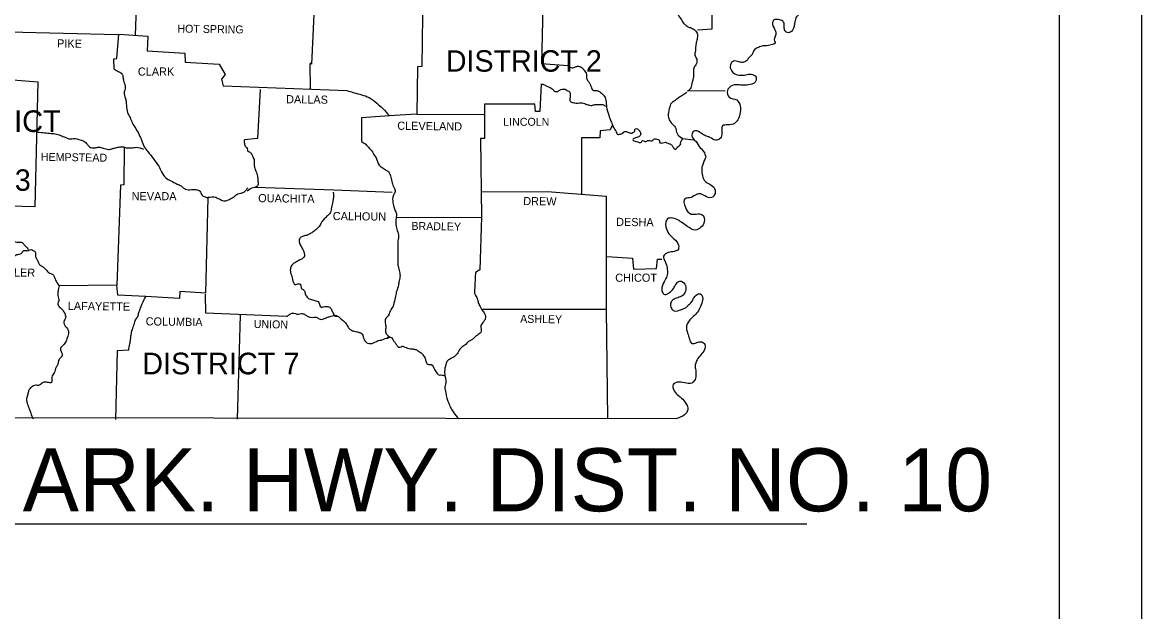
# Model space of a CAD drawing. Extents: x 1369885 to 1370219, y 379980 to 380218.
# Drawn here: x 1370154 to 1370218.7, y 380128.7 to 380162.7 of the extents above; entities that cross this region are included whole.
import ezdxf

# ---------------------------------------------------------------- set-up
doc = ezdxf.new("R2010")
doc.units = 0
for name, color, linetype in [('Default', 7, 'Continuous'), ('Level 2', 7, 'Continuous'), ('R_No Plot', 7, 'Continuous'), ('STAMP_PE_FOSTER-SIGNATURE', 7, 'Continuous')]:
    doc.layers.add(name, color=color, linetype=linetype)

msp = doc.modelspace()

# ---------------------------------------------------------------- linework, layer by layer
at = {"layer": 'Default'}
for p, q in [((1370170.674, 380160.32), (1370170.76, 380160.406)), ((1370170.621, 380158.853), (1370170.665, 380158.897)), ((1370192.473, 380158.751), (1370194.665, 380158.781)), ((1370192.174, 380156.012), (1370192.862, 380155.922)), ((1370161.151, 380146.826), (1370161.171, 380146.866)), ((1370149.848, 380133.736), (1370199.392, 380133.736))]:
    msp.add_line(p, q, dxfattribs=at)
for points in [[(1370193.061, 380162.288), (1370193.918, 380162.348), (1370193.908, 380164.569), (1370193.111, 380164.629), (1370193.151, 380168.973), (1370192.463, 380169.072), (1370192.433, 380172.001), (1370201.788, 380172.071)], [(1370160.812, 380168.853), (1370160.551, 380161.977)], [(1370177.191, 380164.589), (1370177.131, 380160.166), (1370176.872, 380160.156), (1370176.842, 380157.406)], [(1370184.144, 380164.47), (1370184.055, 380160.345), (1370185.579, 380160.216)], [(1370170.884, 380163.165), (1370170.755, 380160.296), (1370170.655, 380160.325), (1370170.665, 380158.851)], [(1370153.261, 380162.258), (1370153.261, 380160.804), (1370153.5, 380160.754), (1370153.48, 380159.399), (1370154.925, 380159.289), (1370154.755, 380152.047), (1370151.767, 380152.126)], [(1370153.281, 380162.178), (1370159.547, 380162.019)], [(1370159.338, 380160.017), (1370159.318, 380160.614), (1370159.497, 380160.624), (1370159.607, 380162.039), (1370161.291, 380161.929), (1370161.251, 380161.063), (1370163.433, 380160.943), (1370163.443, 380160.415), (1370165.415, 380160.296), (1370165.754, 380159.708), (1370165.545, 380159.439), (1370165.644, 380159.04), (1370172.787, 380158.771)], [(1370184.025, 380159.17), (1370183.955, 380157.556), (1370183.706, 380157.556), (1370183.656, 380157.984), (1370180.747, 380157.984), (1370180.747, 380157.367)], [(1370167.786, 380158.831), (1370167.627, 380156.012), (1370166.87, 380155.922)], [(1370175.268, 380157.307), (1370173.644, 380157.207), (1370173.634, 380155.832)], [(1370176.842, 380157.406), (1370175.238, 380157.307)], [(1370176.842, 380157.406), (1370180.717, 380157.387)], [(1370180.747, 380157.387), (1370180.757, 380156.012), (1370180.528, 380156.002), (1370180.588, 380151.449)], [(1370188.149, 380156.799), (1370188.02, 380156.51), (1370187.442, 380156.45), (1370187.412, 380156.052), (1370186.366, 380156.052), (1370186.356, 380152.784)], [(1370159.926, 380155.504), (1370159.896, 380153.332), (1370159.707, 380153.302), (1370159.487, 380147.534)], [(1370167.517, 380153.192), (1370172.05, 380153.033), (1370175.417, 380152.903)], [(1370164.758, 380152.585), (1370164.618, 380147.055), (1370163.134, 380147.155), (1370163.124, 380146.757), (1370161.171, 380146.866)], [(1370180.558, 380152.943), (1370184.623, 380152.913), (1370187.781, 380152.674)], [(1370187.781, 380152.674), (1370187.781, 380146.119), (1370187.87, 380139.813)], [(1370175.637, 380151.439), (1370180.588, 380151.449)], [(1370180.588, 380151.449), (1370180.478, 380148.41), (1370180.239, 380148.251)], [(1370151.687, 380148.749), (1370151.707, 380139.883), (1370191.865, 380139.813)], [(1370187.831, 380149.177), (1370189.305, 380149.088), (1370189.365, 380148.45), (1370190.7, 380148.49), (1370190.75, 380149.028), (1370190.999, 380149.028)], [(1370161.171, 380146.866), (1370159.557, 380146.956), (1370159.487, 380147.534), (1370156.16, 380147.494)], [(1370169.31, 380145.72), (1370164.638, 380145.9), (1370164.618, 380147.006)], [(1370180.658, 380146.129), (1370187.781, 380146.129)], [(1370166.631, 380145.8), (1370166.451, 380139.783)], [(1370160.185, 380143.768), (1370159.507, 380143.728), (1370159.428, 380139.753)]]:
    msp.add_lwpolyline(points, dxfattribs=at)
for points in [[(1370201.091, 380169.411), (1370200.842, 380169.102), (1370200.473, 380169.292), (1370200.473, 380169.561), (1370200.523, 380169.83), (1370200.393, 380170.009), (1370200.164, 380169.929), (1370200.164, 380169.591), (1370200.144, 380169.262), (1370200.074, 380168.794), (1370200.224, 380168.644), (1370200.582, 380168.604), (1370200.832, 380168.534), (1370200.981, 380168.285), (1370200.971, 380167.977), (1370200.851, 380167.688), (1370200.682, 380167.439), (1370200.403, 380167.359), (1370200.184, 380167.498), (1370200.094, 380167.787), (1370199.995, 380168.036), (1370199.815, 380168.226), (1370199.616, 380168.016), (1370199.566, 380167.628), (1370199.586, 380167.299), (1370199.586, 380166.851), (1370199.865, 380166.552), (1370200.045, 380166.213), (1370199.985, 380165.904), (1370199.776, 380165.546), (1370199.696, 380165.227), (1370199.606, 380164.799), (1370199.616, 380164.33), (1370199.536, 380163.872), (1370199.387, 380163.563), (1370199.098, 380163.314), (1370198.909, 380163.145), (1370198.759, 380162.985), (1370198.68, 380162.657), (1370198.63, 380162.428), (1370198.421, 380162.149), (1370198.251, 380162.129), (1370198.122, 380162.238), (1370198.082, 380162.428), (1370198.082, 380162.607), (1370197.992, 380162.796), (1370197.723, 380162.876), (1370197.504, 380162.866), (1370197.404, 380162.706), (1370197.544, 380162.278), (1370197.594, 380162.009), (1370197.524, 380161.631), (1370197.564, 380161.591), (1370197.175, 380161.381), (1370196.857, 380161.352), (1370196.588, 380161.272), (1370196.339, 380161.112), (1370196.219, 380160.863), (1370196.04, 380160.674), (1370195.89, 380160.485), (1370195.681, 380160.395)], [(1370189.743, 380165.884), (1370189.773, 380165.436), (1370190.042, 380165.366), (1370190.142, 380165.247), (1370190.202, 380164.998), (1370190.391, 380164.888), (1370190.64, 380164.739), (1370190.789, 380164.629), (1370190.899, 380164.45), (1370190.969, 380164.161), (1370191.148, 380163.982), (1370191.387, 380163.892), (1370191.557, 380163.683), (1370191.666, 380163.384), (1370191.845, 380163.254), (1370192.025, 380163.025), (1370192.104, 380162.926), (1370192.264, 380162.667), (1370192.413, 380162.537), (1370192.523, 380162.457), (1370192.702, 380162.398), (1370192.921, 380162.258), (1370193.061, 380162.039), (1370193.061, 380161.88), (1370193.011, 380161.621), (1370192.961, 380161.362), (1370192.941, 380161.063), (1370192.921, 380160.804), (1370193.021, 380160.584), (1370192.961, 380160.256), (1370192.852, 380160.076), (1370192.842, 380159.837), (1370192.812, 380159.479), (1370192.762, 380159.269), (1370192.672, 380158.931), (1370192.523, 380158.751)], [(1370195.681, 380160.395), (1370195.452, 380160.435), (1370195.143, 380160.475), (1370194.964, 380160.256), (1370195.023, 380159.937), (1370195.233, 380159.748), (1370195.542, 380159.658), (1370195.86, 380159.688), (1370196.159, 380159.718), (1370196.448, 380159.558), (1370196.398, 380159.269), (1370196.119, 380159.12), (1370195.711, 380159.08), (1370195.382, 380159.11), (1370194.994, 380159.03), (1370194.794, 380158.771), (1370194.904, 380158.393), (1370195.332, 380158.233), (1370195.532, 380157.875), (1370195.542, 380157.536), (1370195.392, 380157.088), (1370195.203, 380156.878), (1370194.814, 380156.789), (1370194.515, 380156.739), (1370194.476, 380156.231), (1370194.346, 380155.982), (1370194.117, 380155.902), (1370193.788, 380156.071), (1370193.589, 380156.141), (1370193.35, 380156.251), (1370193.041, 380156.44), (1370192.812, 380156.41), (1370192.872, 380155.922), (1370192.901, 380155.902), (1370193.16, 380155.543), (1370193.42, 380155.255), (1370193.549, 380154.916)], [(1370159.338, 380160.017), (1370159.517, 380159.907), (1370159.727, 380159.807), (1370159.836, 380159.638), (1370159.876, 380159.389), (1370159.956, 380159.11), (1370159.976, 380158.831), (1370159.916, 380158.672), (1370159.996, 380158.323), (1370160.035, 380158.084), (1370160.065, 380157.795), (1370160.155, 380157.416), (1370160.294, 380157.147), (1370160.424, 380156.839), (1370160.643, 380156.49), (1370160.832, 380156.121), (1370160.922, 380155.922), (1370161.081, 380155.524), (1370161.291, 380155.245), (1370161.619, 380154.826), (1370161.918, 380154.398), (1370162.078, 380154.079), (1370162.337, 380153.73), (1370162.616, 380153.561), (1370162.984, 380153.372), (1370163.213, 380153.262), (1370163.472, 380153.073), (1370163.811, 380153.053), (1370164.06, 380153.053), (1370164.299, 380152.953), (1370164.409, 380152.754), (1370164.598, 380152.624), (1370164.758, 380152.585)], [(1370185.579, 380160.216), (1370185.738, 380160.106), (1370185.968, 380160.126), (1370186.127, 380160.186), (1370186.247, 380160.176), (1370186.406, 380160.076), (1370186.516, 380159.947), (1370186.595, 380159.847), (1370186.655, 380159.698), (1370186.655, 380159.548), (1370186.705, 380159.359), (1370186.775, 380159.279), (1370186.854, 380159.14), (1370186.914, 380159), (1370186.944, 380158.921), (1370187.063, 380158.771), (1370187.173, 380158.781), (1370187.273, 380158.771), (1370187.412, 380158.702), (1370187.601, 380158.542), (1370187.641, 380158.502), (1370187.771, 380158.213), (1370187.791, 380158.044), (1370187.811, 380157.805), (1370187.86, 380157.586), (1370187.94, 380157.347), (1370187.99, 380157.187), (1370188.09, 380156.958), (1370188.149, 380156.799), (1370188.239, 380156.599), (1370188.369, 380156.38), (1370188.428, 380156.251), (1370188.608, 380156.261)], [(1370150.9, 380159.399), (1370150.96, 380159.07), (1370151.059, 380158.781), (1370151.069, 380158.562), (1370151.169, 380158.233), (1370151.169, 380158.114), (1370151.199, 380157.875), (1370151.159, 380157.745), (1370151.209, 380157.476), (1370151.199, 380157.287), (1370151.199, 380157.118), (1370151.209, 380156.849), (1370151.298, 380156.599), (1370151.388, 380156.241), (1370151.438, 380156.052), (1370151.527, 380155.773), (1370151.587, 380155.424), (1370151.597, 380155.155), (1370151.567, 380154.916), (1370151.637, 380154.647), (1370151.757, 380154.368), (1370151.916, 380154.109), (1370152.095, 380153.81), (1370152.225, 380153.581), (1370152.394, 380153.332), (1370152.524, 380153.123), (1370152.723, 380152.854), (1370152.813, 380152.634), (1370152.813, 380152.326), (1370152.852, 380152.047), (1370152.842, 380151.728), (1370152.823, 380151.439), (1370152.743, 380151.05), (1370152.803, 380150.861), (1370153.012, 380150.592), (1370153.141, 380150.512), (1370153.37, 380150.463), (1370153.48, 380150.313), (1370153.54, 380150.084), (1370153.779, 380150.004), (1370154.028, 380149.984), (1370154.148, 380149.855), (1370154.317, 380149.676), (1370154.367, 380149.586)], [(1370184.025, 380159.17), (1370184.214, 380159.1), (1370184.364, 380159.03), (1370184.543, 380158.961), (1370184.663, 380158.871), (1370184.832, 380158.731), (1370185.031, 380158.751), (1370185.171, 380158.841), (1370185.31, 380158.861), (1370185.42, 380158.851), (1370185.539, 380158.781), (1370185.679, 380158.682), (1370185.699, 380158.542), (1370185.699, 380158.383), (1370185.699, 380158.154), (1370185.778, 380158.114), (1370186.047, 380158.054), (1370186.237, 380158.064), (1370186.406, 380158.064), (1370186.555, 380158.024), (1370186.675, 380157.964), (1370186.765, 380157.944), (1370186.894, 380157.915), (1370187.004, 380157.934), (1370187.193, 380157.974), (1370187.293, 380157.974), (1370187.472, 380157.974), (1370187.582, 380157.964), (1370187.751, 380157.875)], [(1370172.787, 380158.771), (1370173.644, 380158.532), (1370174.082, 380158.373), (1370174.521, 380158.054), (1370174.879, 380157.735), (1370175.238, 380157.327)], [(1370192.453, 380158.682), (1370192.214, 380158.502), (1370192.025, 380158.393), (1370191.816, 380158.233), (1370191.557, 380158.054), (1370191.437, 380157.735), (1370191.377, 380157.297), (1370191.457, 380157.028), (1370191.656, 380156.799), (1370191.796, 380156.619), (1370191.885, 380156.291), (1370192.134, 380156.052), (1370192.204, 380156.022)], [(1370154.905, 380156.37), (1370155.323, 380156.34), (1370155.702, 380156.301), (1370156.001, 380156.261), (1370156.309, 380156.151), (1370156.578, 380156.052), (1370156.758, 380155.982), (1370157.047, 380156.002), (1370157.306, 380155.942), (1370157.585, 380155.852), (1370157.794, 380155.663), (1370157.923, 380155.524), (1370158.182, 380155.464), (1370158.392, 380155.494), (1370158.641, 380155.474), (1370158.93, 380155.384), (1370159.159, 380155.394), (1370159.338, 380155.444), (1370159.557, 380155.494), (1370159.836, 380155.524), (1370160.045, 380155.474), (1370160.314, 380155.464), (1370160.633, 380155.494), (1370161.032, 380155.384)], [(1370188.608, 380156.261), (1370188.747, 380156.321), (1370188.847, 380156.41), (1370188.966, 380156.4), (1370189.096, 380156.35), (1370189.265, 380156.321), (1370189.385, 380156.38), (1370189.435, 380156.43), (1370189.444, 380156.53), (1370189.544, 380156.58), (1370189.654, 380156.51), (1370189.773, 380156.33), (1370189.773, 380156.221), (1370189.733, 380156.151), (1370189.584, 380156.071), (1370189.395, 380156.002), (1370189.335, 380155.922), (1370189.524, 380155.832), (1370189.823, 380155.812), (1370189.893, 380155.882), (1370190.092, 380155.822), (1370190.172, 380155.882), (1370190.431, 380155.872), (1370190.55, 380155.962), (1370190.789, 380155.942), (1370190.869, 380155.892), (1370190.869, 380155.793), (1370191.068, 380155.753), (1370191.208, 380155.783), (1370191.397, 380155.723), (1370191.557, 380155.643), (1370191.646, 380155.524), (1370191.756, 380155.384), (1370191.855, 380155.424), (1370191.935, 380155.524), (1370192.094, 380155.693), (1370192.094, 380155.802), (1370192.144, 380155.882), (1370192.194, 380155.992)], [(1370166.87, 380155.922), (1370166.87, 380155.713), (1370166.949, 380155.524), (1370167.029, 380155.434), (1370167.059, 380155.284), (1370167.159, 380155.225), (1370167.298, 380155.095), (1370167.378, 380154.906), (1370167.428, 380154.786), (1370167.428, 380154.627), (1370167.437, 380154.477), (1370167.467, 380154.288), (1370167.597, 380153.959), (1370167.627, 380153.83), (1370167.647, 380153.72), (1370167.657, 380153.531), (1370167.657, 380153.312), (1370167.517, 380153.192)], [(1370173.634, 380155.832), (1370173.883, 380155.673), (1370174.092, 380155.454), (1370174.242, 380155.284), (1370174.341, 380155.105), (1370174.481, 380154.886), (1370174.66, 380154.468), (1370174.83, 380154.328), (1370175.059, 380154.179), (1370175.198, 380154.079), (1370175.338, 380153.77), (1370175.407, 380153.451), (1370175.527, 380153.162), (1370175.587, 380152.943), (1370175.487, 380152.724), (1370175.457, 380152.286), (1370175.527, 380151.987), (1370175.617, 380151.768), (1370175.666, 380151.519), (1370175.637, 380151.439)], [(1370193.549, 380154.916), (1370193.429, 380154.667), (1370193.31, 380154.228), (1370193.35, 380153.85), (1370193.509, 380153.531), (1370193.778, 380153.362), (1370194.057, 380153.113), (1370194.037, 380152.724), (1370193.868, 380152.585), (1370193.489, 380152.684), (1370193.19, 380152.814), (1370192.941, 380152.734), (1370192.603, 380152.575), (1370192.354, 380152.535), (1370192.363, 380152.017), (1370192.702, 380151.638), (1370192.991, 380151.638), (1370193.34, 380151.598), (1370193.459, 380151.2), (1370193.26, 380150.871), (1370192.931, 380150.712), (1370192.513, 380150.901), (1370192.214, 380151.11), (1370191.925, 380151.309), (1370191.547, 380151.409), (1370191.337, 380151.369), (1370191.238, 380150.901), (1370191.417, 380150.493), (1370191.706, 380150.204), (1370191.965, 380149.835), (1370191.925, 380149.556), (1370191.726, 380149.476), (1370191.377, 380149.407), (1370191.168, 380149.297), (1370191.108, 380149.207), (1370191.218, 380148.839), (1370191.317, 380148.43), (1370191.317, 380148.121), (1370191.198, 380147.833), (1370191.009, 380147.394), (1370191.038, 380147.115), (1370191.168, 380146.986), (1370191.327, 380147.026), (1370191.547, 380147.175), (1370191.696, 380147.354), (1370191.816, 380147.574), (1370192.045, 380147.763), (1370192.324, 380147.593), (1370192.393, 380147.255), (1370192.234, 380146.956), (1370191.995, 380146.826), (1370191.716, 380146.717), (1370191.507, 380146.478), (1370191.557, 380146.189), (1370191.726, 380146.039), (1370192.134, 380146.119), (1370192.403, 380146.239), (1370192.553, 380146.388), (1370192.742, 380146.577), (1370192.842, 380146.767), (1370192.981, 380146.956)], [(1370167.069, 380153.143), (1370166.949, 380153.003), (1370166.81, 380152.874), (1370166.64, 380152.824), (1370166.491, 380152.784), (1370166.292, 380152.644), (1370166.132, 380152.535), (1370165.933, 380152.435), (1370165.734, 380152.375), (1370165.495, 380152.455), (1370165.355, 380152.525), (1370165.216, 380152.585), (1370164.758, 380152.585)], [(1370167.029, 380152.963), (1370167.308, 380153.152), (1370167.627, 380153.192)], [(1370172.01, 380152.903), (1370171.99, 380152.355), (1370171.911, 380152.017), (1370171.831, 380151.708), (1370171.671, 380151.529), (1370171.492, 380151.359), (1370171.333, 380151.16), (1370171.193, 380150.921), (1370171.044, 380150.761), (1370170.855, 380150.612), (1370170.675, 380150.502), (1370170.466, 380150.403), (1370170.237, 380150.343), (1370170.068, 380150.224), (1370170.058, 380149.965), (1370170.247, 380149.586), (1370170.317, 380149.417), (1370170.337, 380149.207), (1370170.257, 380149.088), (1370170.078, 380148.988), (1370169.878, 380148.869), (1370169.689, 380148.759), (1370169.559, 380148.57), (1370169.53, 380148.321), (1370169.619, 380148.022), (1370169.659, 380147.852), (1370169.799, 380147.574), (1370169.908, 380147.583), (1370170.107, 380147.574), (1370170.127, 380147.524), (1370170.137, 380147.464), (1370170.177, 380147.324), (1370170.346, 380147.205), (1370170.366, 380147.095), (1370170.466, 380146.886), (1370170.625, 380146.737), (1370170.755, 380146.697), (1370171.004, 380146.617), (1370171.134, 380146.587), (1370171.273, 380146.268), (1370171.452, 380146.278), (1370171.582, 380146.298), (1370171.801, 380146.249), (1370171.901, 380146.119), (1370172, 380145.9), (1370172.13, 380145.74), (1370172.219, 380145.74)], [(1370175.637, 380151.439), (1370175.676, 380150.761), (1370175.776, 380150.433), (1370175.746, 380150.084), (1370175.736, 380149.745), (1370175.736, 380149.436), (1370175.736, 380149.138), (1370175.736, 380148.839), (1370175.756, 380148.62), (1370175.836, 380148.301), (1370175.866, 380148.002), (1370175.806, 380147.713), (1370175.766, 380147.454), (1370175.676, 380147.195), (1370175.607, 380146.896), (1370175.517, 380146.508), (1370175.437, 380146.258), (1370175.288, 380145.999), (1370175.188, 380145.75), (1370175.039, 380145.601), (1370175.009, 380145.342), (1370175.049, 380145.093), (1370175.019, 380144.874), (1370175.099, 380144.674), (1370175.298, 380144.525)], [(1370151.687, 380148.749), (1370152.065, 380148.908), (1370152.225, 380148.859), (1370152.374, 380148.709), (1370152.534, 380148.709), (1370152.623, 380148.849), (1370152.793, 380148.859), (1370152.922, 380148.849), (1370153.062, 380148.928), (1370153.181, 380148.988), (1370153.351, 380149.038), (1370153.47, 380149.088), (1370153.58, 380149.207), (1370153.779, 380149.307), (1370154.008, 380149.387), (1370154.068, 380149.496), (1370154.177, 380149.536), (1370154.397, 380149.526), (1370154.546, 380149.586), (1370154.666, 380149.536), (1370154.775, 380149.456), (1370154.795, 380149.177), (1370154.885, 380149.018), (1370155.014, 380148.749), (1370155.204, 380148.6), (1370155.373, 380148.46), (1370155.443, 380148.371), (1370155.632, 380148.211), (1370155.791, 380148.151), (1370155.871, 380148.032), (1370155.991, 380147.753), (1370156.16, 380147.494)], [(1370180.239, 380148.251), (1370180.209, 380147.912), (1370180.199, 380147.593), (1370180.179, 380147.285), (1370180.179, 380147.055), (1370180.309, 380146.806), (1370180.379, 380146.567), (1370180.458, 380146.358), (1370180.618, 380146.079), (1370180.757, 380145.88), (1370180.797, 380145.581), (1370180.707, 380145.422), (1370180.548, 380145.192), (1370180.538, 380144.784), (1370180.339, 380144.645), (1370180.09, 380144.425), (1370179.94, 380144.326), (1370179.791, 380144.236), (1370179.622, 380144.057), (1370179.382, 380143.887), (1370179.213, 380143.618), (1370179.014, 380143.409), (1370178.844, 380143.3), (1370178.615, 380143.16), (1370178.516, 380142.941), (1370178.446, 380142.533), (1370178.476, 380142.234), (1370178.516, 380141.975), (1370178.466, 380141.646), (1370178.516, 380141.287), (1370178.575, 380140.998), (1370178.665, 380140.749), (1370178.785, 380140.46), (1370178.934, 380140.201), (1370179.263, 380139.793)], [(1370156.16, 380147.494), (1370156.1, 380147.175), (1370156.09, 380146.926), (1370156.14, 380146.627), (1370156.09, 380146.488), (1370156.17, 380146.278), (1370156.339, 380146.119), (1370156.459, 380145.94), (1370156.539, 380145.691), (1370156.439, 380145.402), (1370156.549, 380145.113), (1370156.648, 380145.003), (1370156.698, 380144.824), (1370156.628, 380144.485), (1370156.529, 380144.236), (1370156.309, 380143.977), (1370156.24, 380143.858), (1370156.27, 380143.698), (1370156.329, 380143.429), (1370156.27, 380143.359), (1370156.13, 380143.17), (1370156.09, 380142.961), (1370155.991, 380142.782), (1370155.881, 380142.463), (1370155.732, 380142.204), (1370155.712, 380141.905), (1370155.492, 380141.905), (1370155.243, 380141.905), (1370155.014, 380141.745), (1370154.805, 380141.736), (1370154.556, 380141.636), (1370154.397, 380141.427), (1370154.347, 380141.198), (1370154.277, 380140.978), (1370154.347, 380140.6), (1370154.446, 380140.341), (1370154.516, 380140.132), (1370154.656, 380139.793)], [(1370160.185, 380143.768), (1370160.245, 380144.127), (1370160.294, 380144.395), (1370160.324, 380144.655), (1370160.394, 380144.953), (1370160.494, 380145.272), (1370160.583, 380145.531), (1370160.703, 380145.72), (1370160.773, 380145.94), (1370160.872, 380146.209), (1370160.972, 380146.478), (1370161.151, 380146.826)], [(1370192.981, 380146.956), (1370193.24, 380147.016), (1370193.36, 380146.846), (1370193.31, 380146.478), (1370193.16, 380146.129), (1370192.951, 380145.83), (1370192.722, 380145.621), (1370192.433, 380145.173), (1370192.493, 380144.754), (1370192.603, 380144.415), (1370192.752, 380144.156), (1370193.021, 380144.206), (1370193.31, 380144.246), (1370193.489, 380144.097), (1370193.469, 380143.798), (1370193.25, 380143.499), (1370193.041, 380143.21), (1370192.931, 380142.821), (1370192.971, 380142.542), (1370192.971, 380142.293), (1370192.892, 380142.014), (1370192.732, 380141.865), (1370192.324, 380141.875), (1370191.895, 380141.915), (1370191.666, 380141.785), (1370191.716, 380141.417), (1370191.965, 380141.138), (1370192.144, 380140.998), (1370192.393, 380140.689), (1370192.503, 380140.44), (1370192.473, 380140.221), (1370192.314, 380140.032), (1370191.865, 380139.813)], [(1370169.31, 380145.72), (1370169.49, 380145.84), (1370169.659, 380145.91), (1370169.818, 380145.88), (1370169.998, 380145.85), (1370170.147, 380145.88), (1370170.346, 380145.84), (1370170.506, 380145.74), (1370170.695, 380145.671), (1370170.884, 380145.671), (1370171.044, 380145.671), (1370171.193, 380145.571), (1370171.452, 380145.581), (1370171.671, 380145.671), (1370171.891, 380145.73), (1370172.19, 380145.77), (1370172.449, 380145.581), (1370172.638, 380145.422), (1370172.787, 380145.252), (1370172.897, 380145.053), (1370173.016, 380144.943), (1370173.216, 380144.864), (1370173.365, 380144.834), (1370173.554, 380144.784), (1370173.654, 380144.734), (1370173.744, 380144.525), (1370173.883, 380144.246), (1370174.162, 380144.146), (1370174.501, 380144.276), (1370174.77, 380144.356), (1370174.969, 380144.415), (1370175.089, 380144.465), (1370175.198, 380144.475), (1370175.168, 380144.495), (1370175.298, 380144.525), (1370175.417, 380144.435), (1370175.497, 380144.316), (1370175.627, 380144.146), (1370175.746, 380143.987), (1370175.866, 380143.937), (1370175.985, 380143.997), (1370176.155, 380143.947), (1370176.294, 380143.887), (1370176.463, 380143.848), (1370176.603, 380143.838), (1370176.792, 380143.798), (1370176.932, 380143.718), (1370177.061, 380143.638), (1370177.191, 380143.499), (1370177.33, 380143.28), (1370177.37, 380143.1), (1370177.519, 380142.931), (1370177.669, 380142.931), (1370177.868, 380142.642), (1370177.948, 380142.533), (1370178.117, 380142.333), (1370178.237, 380142.333), (1370178.466, 380142.293)]]:
    msp.add_spline(points, degree=3, dxfattribs=at)
at = {"layer": 'R_No Plot'}
msp.add_lwpolyline([(1369885.401, 380217.922), (1370218.741, 380217.922), (1370218.741, 380004.585), (1369885.401, 380004.585)], close=True, dxfattribs=at)
at = {"layer": 'STAMP_PE_FOSTER-SIGNATURE'}
msp.add_line((1370213.988, 380008.568), (1370213.988, 380214.028), dxfattribs=at)

# ---------------------------------------------------------------- texts
at = {"layer": 'Default'}
for s, height, rotation, p in [('HOT SPRING', 0.4603, 359.22157, (1370162.994, 380162.129)), ('PIKE', 0.4711, 359.04516, (1370156.04, 380161.272)), ('DALLAS', 0.4711, 359.24615, (1370169.281, 380158.044)), ('CLEVELAND', 0.4713, 359.33765, (1370175.706, 380156.51)), ('HEMPSTEAD', 0.4601, 359.1885, (1370155.104, 380154.717)), ('OUACHITA', 0.4713, 359.20428, (1370167.667, 380152.326)), ('DREW', 0.4711, 359.22578, (1370182.989, 380152.156)), ('CALHOUN', 0.4713, 359.36341, (1370171.98, 380151.29)), ('BRADLEY', 0.4601, 359.1449, (1370176.523, 380150.722)), ('DESHA', 0.4711, 359.3704, (1370188.359, 380150.951)), ('MILLER', 0.4711, 359.13195, (1370152.494, 380148.042)), ('LAFAYETTE', 0.4711, 359.18387, (1370156.658, 380146.099)), ('COLUMBIA', 0.4711, 359.21248, (1370161.161, 380145.202)), ('UNION', 0.4603, 358.95837, (1370167.408, 380145.053)), ('ASHLEY', 0.4603, 359.2361, (1370182.81, 380145.352))]:
    msp.add_text(s, height=height, rotation=rotation, dxfattribs=at).set_placement(p)
for s, height, p in [('DISTRICT 2', 1.2383, (1370178.516, 380159.867)), ('CLARK', 0.4712, (1370160.713, 380159.638)), ('DISTRICT', 1.2493, (1370148.549, 380156.38)), ('LINCOLN', 0.4603, (1370181.833, 380156.739)), ('3', 1.238, (1370153.6, 380152.983)), ('NEVADA', 0.4712, (1370160.354, 380152.435)), ('CHICOT', 0.4712, (1370188.309, 380147.723)), ('DISTRICT 7', 1.2493, (1370160.962, 380142.373))]:
    msp.add_text(s, height=height, dxfattribs=at).set_placement(p)
at = {"layer": 'Level 2'}
msp.add_text('ARK. HWY. DIST. NO. 10', height=3.64368, dxfattribs=at).set_placement((1370154.055, 380134.453))

doc.saveas('drawing.dxf')
